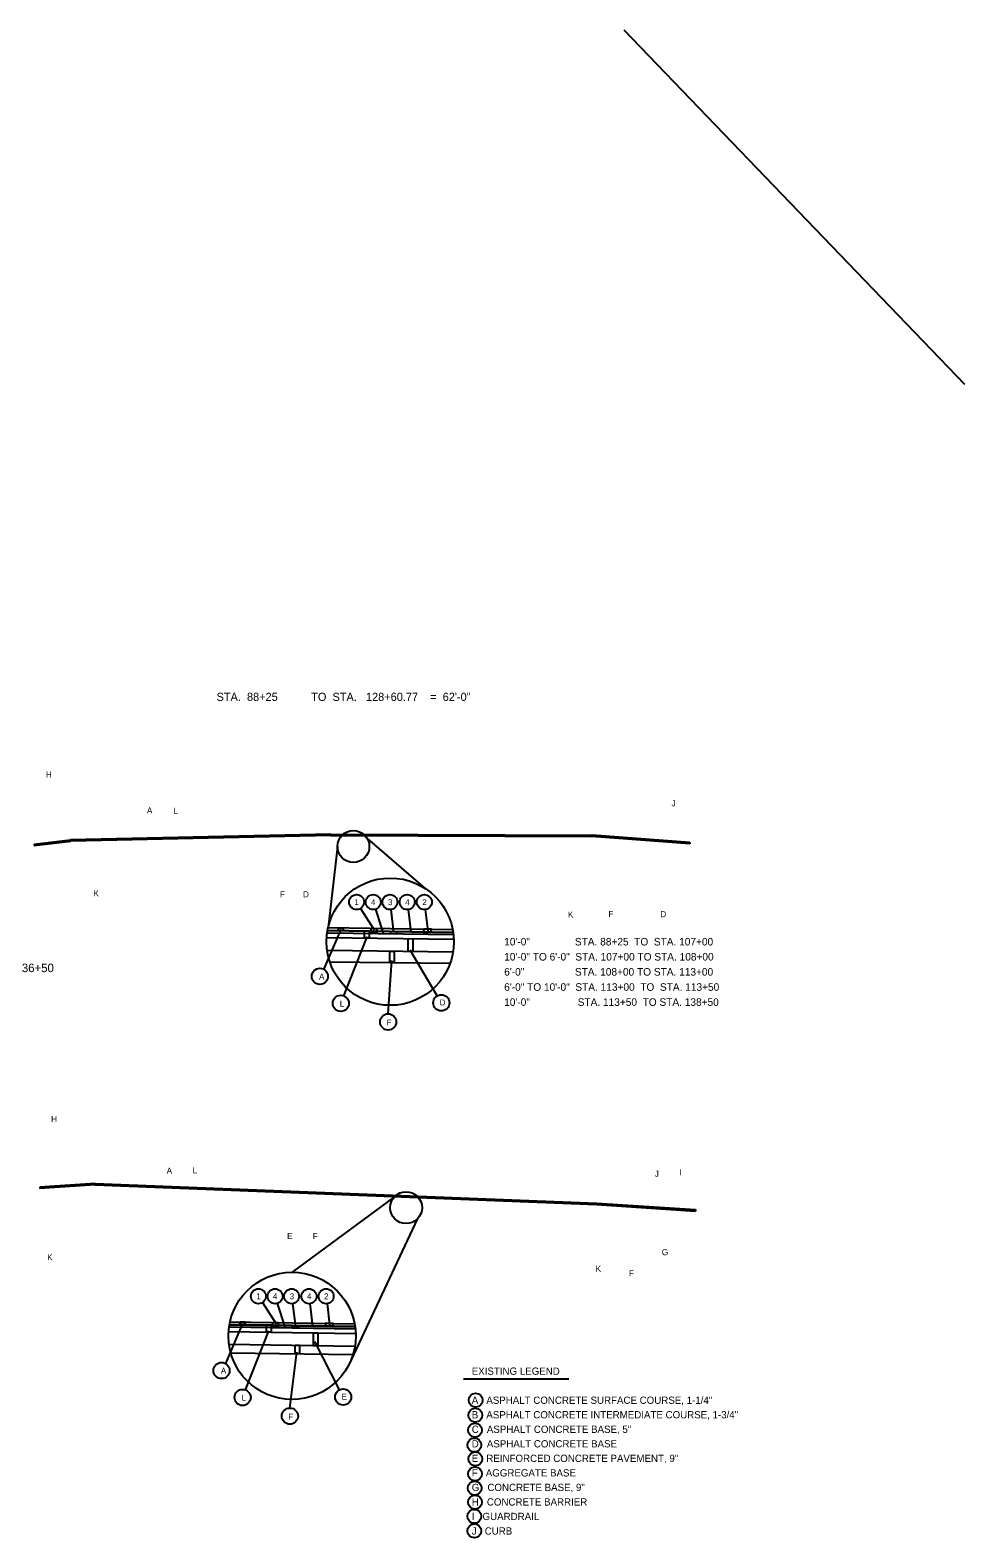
# Model space of a CAD drawing. Extents: x -210 to 558, y -150 to 205.
# Drawn here: x -141.5 to -55.3, y 65.7 to 204.7 of the extents above; entities that cross this region are included whole.
import ezdxf

# ---------------------------------------------------------------- set-up
doc = ezdxf.new("R2010")
doc.units = 0
for name, color, linetype in [('Level 1', 7, 'Continuous'), ('Level 3', 7, 'Continuous'), ('Level 59', 7, 'Continuous'), ('SC_Scratch1', 7, 'Continuous')]:
    doc.layers.add(name, color=color, linetype=linetype)

msp = doc.modelspace()

# ---------------------------------------------------------------- linework, layer by layer
at = {"layer": 'Level 1'}
for p, q in [((-55.32, 172.06), (-55.32, 172.06)), ((-141.11, 129.68), (-137.74, 130.08)), ((-141.11, 129.55), (-137.73, 129.94)), ((-141.11, 129.68), (-141.11, 129.55)), ((-113.76, 130.6), (-137.74, 130.08)), ((-113.76, 130.47), (-137.73, 129.94)), ((-113.15, 129.46), (-114, 122)), ((-113.76, 130.6), (-89.68, 130.51)), ((-113.76, 130.47), (-89.69, 130.37)), ((-110.42, 130.21), (-105.02, 125.56)), ((-80.67, 129.7), (-89.69, 130.37)), ((-80.67, 129.83), (-89.68, 130.51)), ((-80.67, 129.83), (-80.67, 129.7)), ((-111.01, 123.75), (-109.75, 121.78)), ((-109.64, 123.67), (-108.92, 121.43)), ((-108.23, 123.64), (-107.97, 121.52)), ((-106.63, 123.64), (-106.38, 121.58)), ((-105.06, 123.64), (-104.82, 121.69)), ((-114.39, 118.12), (-112.81, 121.8)), ((-114.13, 121.07), (-102.41, 120.9)), ((-114.05, 121.75), (-102.48, 121.56)), ((-114.05, 121.75), (-102.48, 121.56)), ((-114.05, 121.75), (-102.48, 121.56)), ((-114.01, 121.7), (-102.48, 121.52)), ((-114.01, 121.51), (-102.48, 121.33)), ((-114, 121.98), (-102.47, 121.8)), ((-114, 121.98), (-102.47, 121.8)), ((-112.57, 115.68), (-110.4, 121.13)), ((-114.1, 119.9), (-102.49, 119.73)), ((-103.95, 115.68), (-106.45, 119.9)), ((-113.85, 118.83), (-102.76, 118.69)), ((-108.48, 114.02), (-108.13, 118.94)), ((-135.48, 98.39), (-140.59, 98.05)), ((-135.48, 98.26), (-140.59, 97.91)), ((-140.59, 98.05), (-140.59, 97.91)), ((-135.48, 98.39), (-89.23, 96.57)), ((-135.48, 98.26), (-89.24, 96.44)), ((-107.86, 97.19), (-117.32, 90.2)), ((-89.24, 96.44), (-80.15, 95.84)), ((-89.23, 96.57), (-80.15, 95.97)), ((-80.15, 95.97), (-80.15, 95.84)), ((-105.76, 95.14), (-112.11, 81.66)), ((-120.06, 87.4), (-118.8, 85.43)), ((-118.69, 87.32), (-117.98, 85.08)), ((-117.28, 87.3), (-117.02, 85.17)), ((-115.69, 87.3), (-115.44, 85.23)), ((-114.11, 87.3), (-113.87, 85.34)), ((-123.45, 81.77), (-121.87, 85.48)), ((-123.1, 85.4), (-111.53, 85.22)), ((-123.1, 85.4), (-111.53, 85.22)), ((-123.06, 85.63), (-111.53, 85.45)), ((-123.06, 85.35), (-111.53, 85.17)), ((-123.06, 85.16), (-111.53, 84.98)), ((-123.19, 84.72), (-111.47, 84.56)), ((-123.15, 83.55), (-111.54, 83.38)), ((-121.62, 79.34), (-119.46, 84.78)), ((-112.96, 79.36), (-115.23, 83.8)), ((-122.98, 82.75), (-111.73, 82.6)), ((-117.53, 77.67), (-116.88, 82.84))]:
    msp.add_line(p, q, dxfattribs=at)
for points in [[(-113.04, 121.97), (-112.63, 121.96), (-112.63, 121.72), (-113.04, 121.73)], [(-110.64, 121.69), (-110.22, 121.68), (-110.22, 121.02), (-110.64, 121.02)], [(-110.03, 121.92), (-109.54, 121.91), (-109.55, 121.44), (-110.04, 121.45)], [(-108.29, 121.42), (-107.66, 121.41), (-107.65, 121.6), (-108.29, 121.61)], [(-105.21, 121.56), (-104.51, 121.55), (-104.51, 121.83), (-105.2, 121.84)], [(-108.33, 119.81), (-107.91, 119.81), (-107.91, 118.76), (-108.33, 118.76)], [(-106.63, 120.96), (-106.21, 120.95), (-106.21, 119.78), (-106.63, 119.79)], [(-122.1, 85.62), (-121.68, 85.61), (-121.68, 85.38), (-122.1, 85.38)], [(-119.69, 85.35), (-119.27, 85.34), (-119.27, 84.67), (-119.69, 84.68)], [(-119.09, 85.57), (-118.6, 85.56), (-118.6, 85.09), (-119.09, 85.1)], [(-117.35, 85.07), (-116.71, 85.06), (-116.71, 85.25), (-117.35, 85.26)], [(-114.26, 85.21), (-113.57, 85.2), (-113.56, 85.48), (-114.26, 85.49)], [(-117.06, 83.46), (-116.64, 83.46), (-116.64, 82.66), (-117.06, 82.67)], [(-115.37, 84.61), (-114.95, 84.6), (-114.95, 83.43), (-115.37, 83.44)]]:
    msp.add_lwpolyline(points, close=True, dxfattribs=at)
for centre, radius in [((-111.68, 129.46), 1.47), ((-108.28, 120.68), 5.87), ((-108.28, 120.68), 5.87), ((-111.38, 124.33), 0.691), ((-109.85, 124.33), 0.691), ((-108.31, 124.33), 0.691), ((-106.72, 124.33), 0.691), ((-105.14, 124.33), 0.691), ((-114.77, 117.48), 0.746), ((-112.84, 114.99), 0.746), ((-103.57, 115.04), 0.746), ((-108.48, 113.28), 0.746), ((-106.82, 96.15), 1.47), ((-117.33, 84.33), 5.87), ((-120.43, 87.98), 0.691), ((-118.9, 87.98), 0.691), ((-117.37, 87.98), 0.691), ((-115.77, 87.98), 0.691), ((-114.19, 87.98), 0.691), ((-123.83, 81.13), 0.746), ((-121.89, 78.65), 0.746), ((-112.62, 78.69), 0.746), ((-117.53, 76.93), 0.746)]:
    msp.add_circle(centre, radius, dxfattribs=at)
at = {"layer": 'Level 59'}
msp.add_line((-101.53, 80.36), (-91.82, 80.36), dxfattribs=at)
for centre in [(-100.41, 78.4), (-100.44, 77.02), (-100.47, 75.64), (-100.53, 74.26), (-100.44, 72.98), (-100.5, 70.29), (-100.47, 71.6), (-100.47, 69), (-100.53, 67.69), (-100.53, 66.34)]:
    msp.add_circle(centre, 0.639, dxfattribs=at)
at = {"layer": 'SC_Scratch1'}
msp.add_line((-55.32, 172.06), (-86.71, 204.74), dxfattribs=at)

# ---------------------------------------------------------------- texts
at = {"layer": 'Level 1'}
for s, p in [('1', (-111.58, 124.05)), ('4', (-110.05, 124.05)), ('3', (-108.49, 124.05)), ('4', (-106.9, 124.05)), ('2', (-105.32, 124.05)), ('1', (-120.63, 87.7)), ('4', (-119.1, 87.7)), ('3', (-117.55, 87.7)), ('4', (-115.95, 87.7)), ('2', (-114.38, 87.7))]:
    msp.add_text(s, height=0.547, dxfattribs=at).set_placement(p)
at = {"layer": 'Level 3'}
for s, p in [('H', (-140.02, 135.82)), ('J', (-82.36, 133.16)), ('A', (-130.71, 132.51)), ('L', (-128.27, 132.48)), ('K', (-135.63, 124.85)), ('F', (-118.45, 124.77)), ('D', (-116.32, 124.77)), ('K', (-91.9, 122.9)), ('F', (-88.17, 122.96)), ('D', (-83.39, 122.94)), ('H', (-139.54, 104.04)), ('A', (-128.89, 99.28)), ('L', (-126.49, 99.31)), ('J', (-83.9, 99)), ('I', (-81.65, 99.12)), ('E', (-117.79, 93.25)), ('F', (-115.42, 93.25)), ('K', (-139.9, 91.3)), ('G', (-83.25, 91.77)), ('K', (-89.35, 90.23)), ('F', (-86.27, 89.81))]:
    msp.add_text(s, height=0.562, dxfattribs=at).set_placement(p)
at = {"layer": 'Level 59'}
for s, height, p in [('STA.  88+25           TO  STA.   128+60.77    =  62\'-0"', 0.7548, (-124.29, 142.88)), ('10\'-0"                STA. 88+25  TO  STA. 107+00', 0.697, (-97.78, 120.33)), ('10\'-0" TO 6\'-0"  STA. 107+00 TO STA. 108+00', 0.697, (-97.78, 118.94)), ('STA.  88+25     TO  STA.   136+50', 0.7854, (-155.4, 117.87)), ('6\'-0"                  STA. 108+00 TO STA. 113+00', 0.697, (-97.78, 117.55)), ('A', 0.547, (-114.84, 117.19)), ('6\'-0" TO 10\'-0"  STA. 113+00  TO  STA. 113+50', 0.697, (-97.78, 116.15)), ('10\'-0"                 STA. 113+50  TO STA. 138+50', 0.697, (-97.78, 114.76)), ('L', 0.547, (-112.93, 114.7)), ('D', 0.547, (-103.72, 114.8)), ('F', 0.547, (-108.61, 112.95)), ('A', 0.547, (-123.89, 80.84)), ('EXISTING LEGEND', 0.6698, (-100.77, 80.74)), ('L', 0.547, (-121.98, 78.36)), ('E', 0.547, (-112.77, 78.45)), ('A   ASPHALT CONCRETE SURFACE COURSE, 1-1/4"', 0.6698, (-100.77, 78.06)), ('F', 0.547, (-117.67, 76.6)), ('B   ASPHALT CONCRETE INTERMEDIATE COURSE, 1-3/4"', 0.6698, (-100.77, 76.72)), ('C   ASPHALT CONCRETE BASE, 5"', 0.6698, (-100.77, 75.38)), ('D   ASPHALT CONCRETE BASE', 0.6698, (-100.77, 74.04)), ('E   REINFORCED CONCRETE PAVEMENT, 9"', 0.6698, (-100.77, 72.7)), ('F   AGGREGATE BASE', 0.6698, (-100.77, 71.36)), ('G   CONCRETE BASE, 9"', 0.6698, (-100.77, 70.02)), ('H   CONCRETE BARRIER', 0.6698, (-100.77, 68.68)), ('I   GUARDRAIL ', 0.6698, (-100.77, 67.34)), ('J   CURB', 0.67, (-100.77, 66))]:
    msp.add_text(s, height=height, dxfattribs=at).set_placement(p)

doc.saveas('drawing.dxf')
